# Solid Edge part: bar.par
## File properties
Author: edge
Template: normal.par
Last saved by: edge
Revision: 40
Application: Solid Edge
文書内容のタイプ: 0
Accuracy: 0.99
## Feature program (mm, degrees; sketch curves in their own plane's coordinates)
sketch for "unnamed Protrusion 1" plane through (0, 0, 0) normal (1, 0, 0) x-axis (0, 1, 0)
  circle centre (0, 0) radius 14
extrude "unnamed Protrusion 1" add finite 450 symmetric
sketch for "unnamed Protrusion 2" plane through (225, 0, 0) normal (1, 0, 0) x-axis (0, 1, 0)
extrude "unnamed Protrusion 2" add finite 10 along +normal
mirror "unnamed Mirror 1" of "unnamed Protrusion 2" about plane through (0, 0, 0) normal (1, 0, 0)
extrude "unnamed Protrusion 3" add finite 10
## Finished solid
Body 1: solid body, 13 faces, 26 edges, 16 vertices.
  Faces by surface: plane 10, cylinder 3
  Edges by curve: line 20, circle 6
Bounding box of the edges (mm): 470.000 x 56.000 x 52.000, from (-235, -30, -26) to (235, 26, 26).
Cylindrical faces by radius (mm): R14 x1, R26 x2
Planar faces by outward normal: +x 2, +z 2, -x 2, -y 2, -z 2
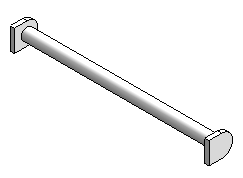
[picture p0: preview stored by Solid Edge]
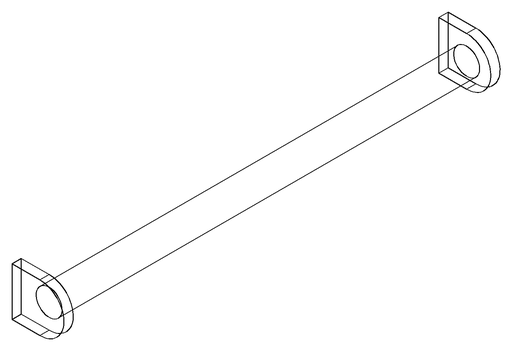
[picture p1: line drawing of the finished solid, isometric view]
